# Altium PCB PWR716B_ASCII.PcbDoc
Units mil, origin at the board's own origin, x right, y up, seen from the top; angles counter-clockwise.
Board outline 2400 x 2000 mil, 2 copper layers (Top Layer, Bottom Layer), stack 64.8 mil thick; 38 components, 10 nets, 53 pads, 198 vias.
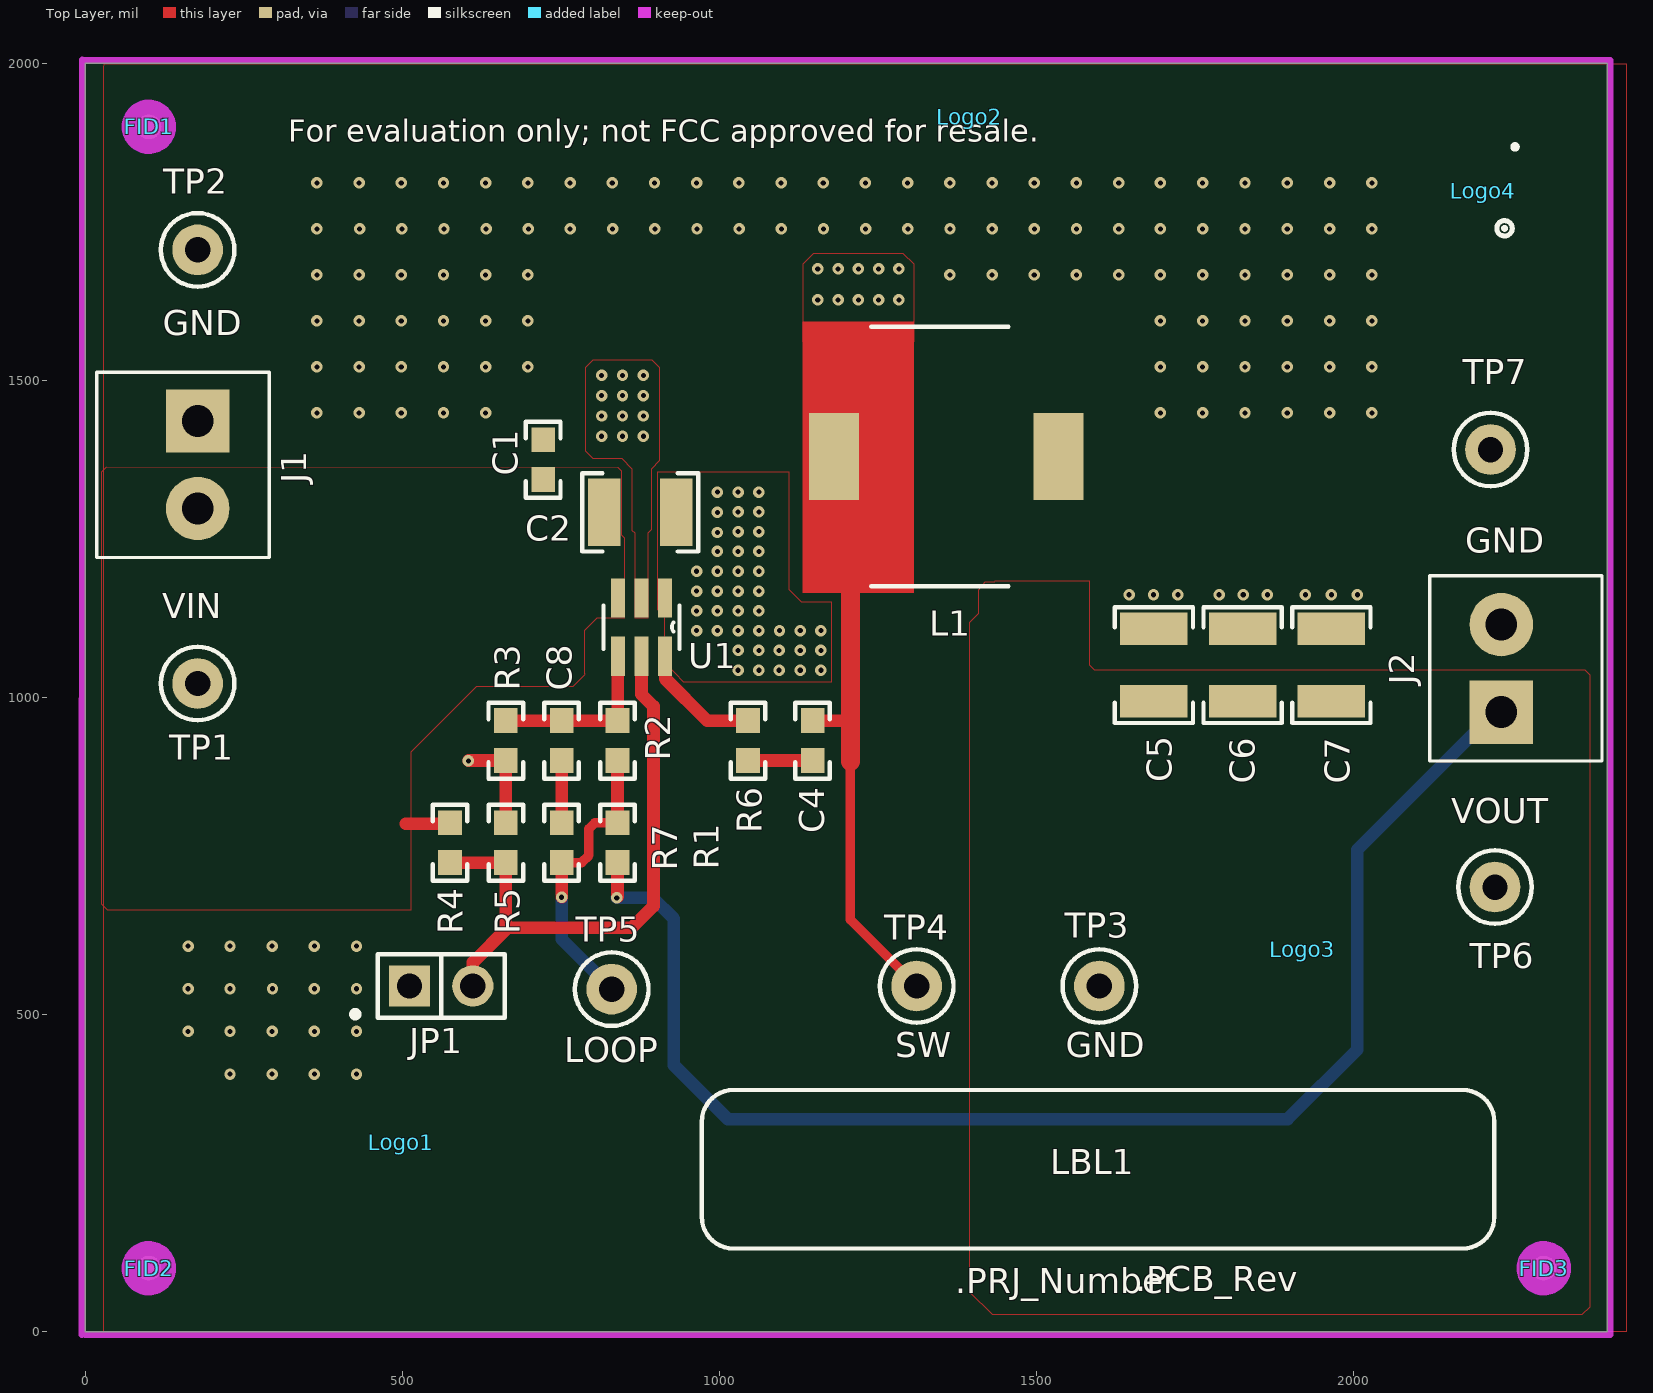
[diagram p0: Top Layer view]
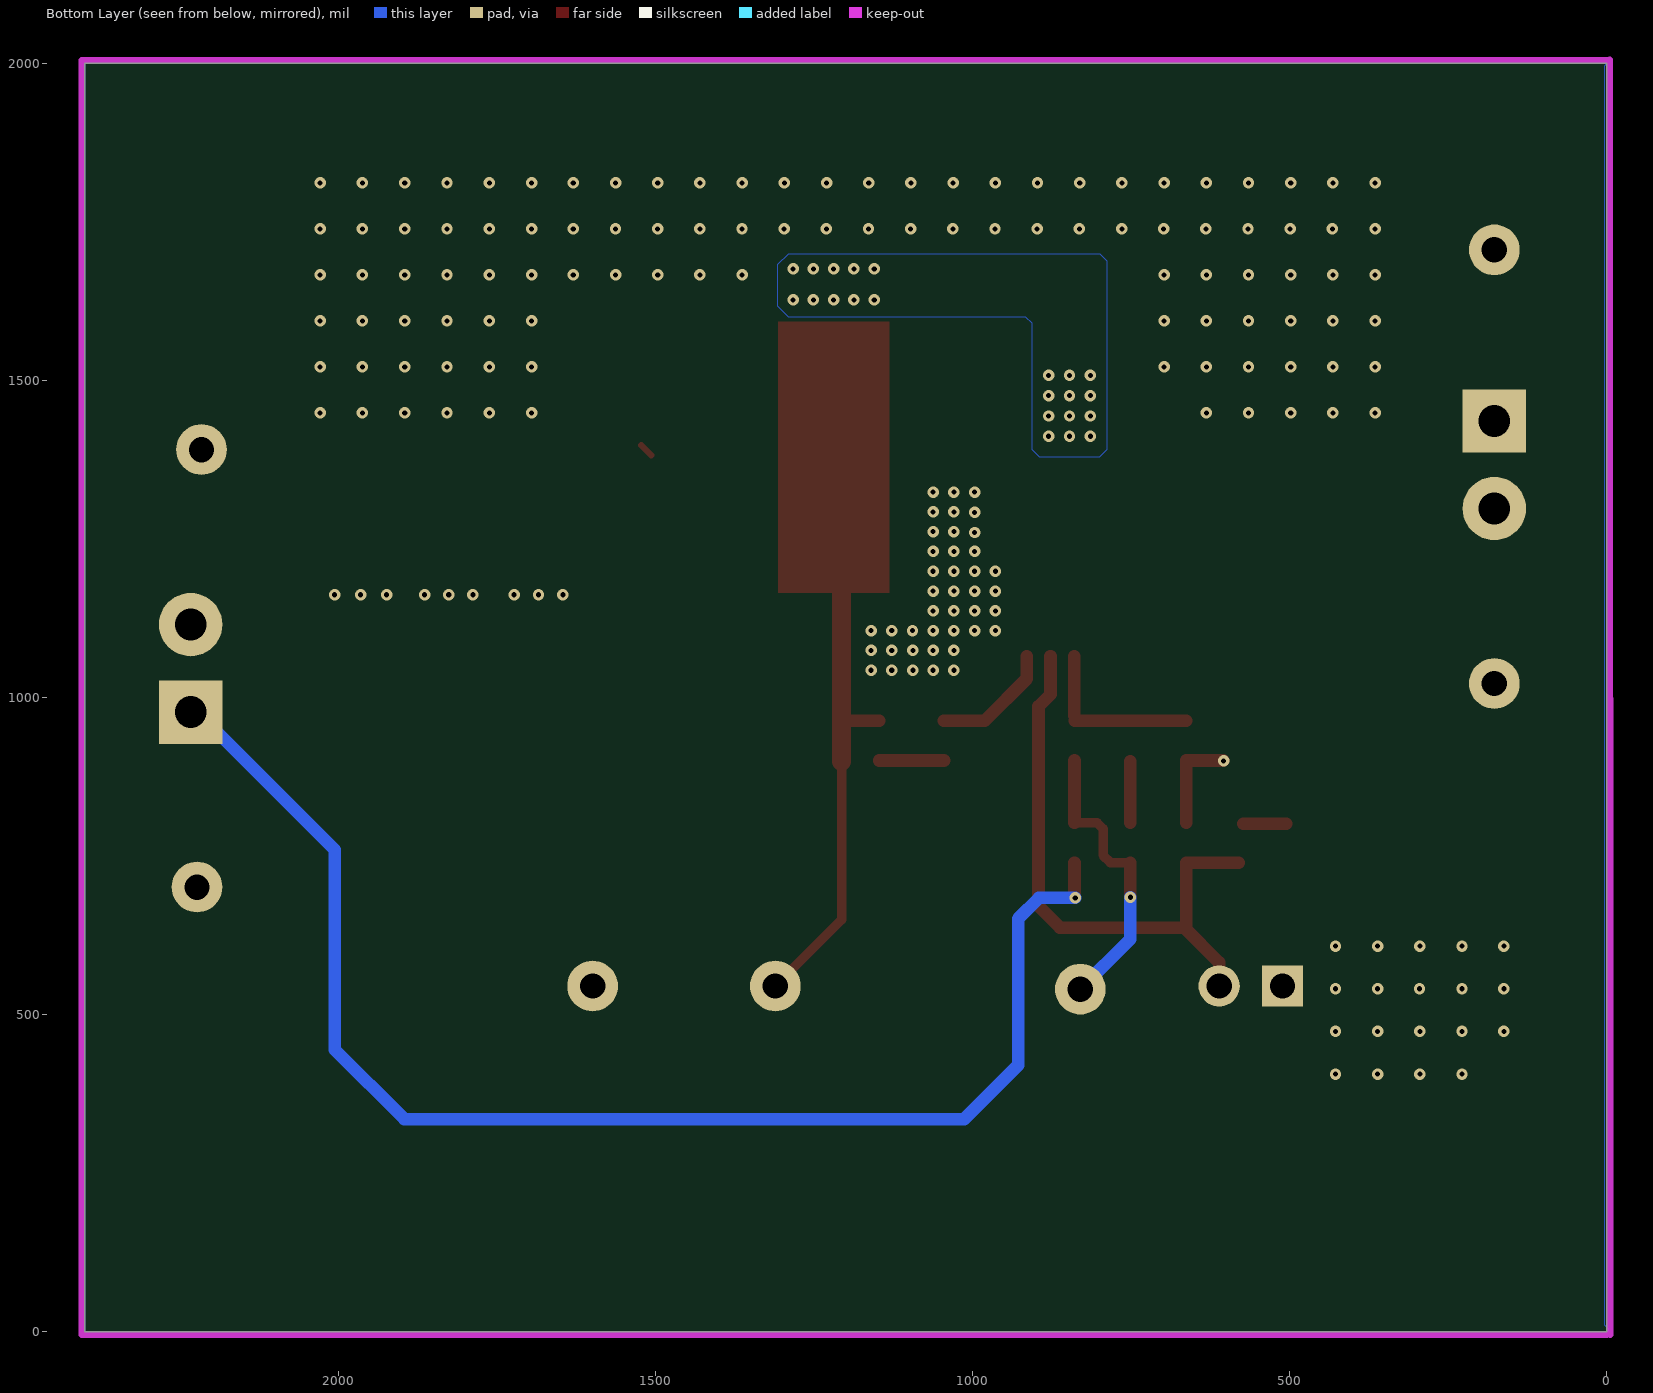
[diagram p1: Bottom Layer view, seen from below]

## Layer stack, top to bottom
Top Solder: solder mask 0.4, Solder Resist, Dk 3.5
Top Layer: signal copper 2.8
Dielectric1: core 59.2, FR-4, Dk 4.8
Bottom Layer: signal copper 2.8
Bottom Solder: solder mask 0.4, Solder Resist, Dk 3.5

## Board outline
0,0 2400,0 2400,2000 0,2000

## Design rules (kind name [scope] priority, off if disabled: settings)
AcuteAngle [All] p0: scope1count=1 scope1_0_kind=Board scope1_0_value=Board scope2count=1 scope2_0_kind=Board scope2_0_value=Board commentlength=0 minimum=4.50000000000000E+0001
AcuteAngle [All] p1: minimum=4.50000000000000E+0001 checktracksonly=FALSE
AssemblyTestPointUsage [All] p0: scope1count=1 scope1_0_kind=Board scope1_0_value=Board scope2count=1 scope2_0_kind=Board scope2_0_value=Board commentlength=0
AssemblyTestPointUsage [All] p1: valid=2
AssemblyTestpoint [All] p0: scope1count=1 scope1_0_kind=Board scope1_0_value=Board scope2count=1 scope2_0_kind=Board scope2_0_value=Board commentlength=0
Clearance Clearance_Keepouts [All] p0 off: scope1count=1 scope1_0_kind=Board scope1_0_value=Board scope2count=1 scope2_0_kind=Board scope2_0_value=Board commentlength=99 gap=0 // Protel DXP Scope 2 Expression Was: ((IsTrack Or IsArc) And Not InPoly) And IsFree and IsKeepOut
Clearance Clearance_BoardEdge_MountingHoles [All] p0 off: scope1count=1 scope1_0_kind=Board scope1_0_value=Board scope2count=1 scope2_0_kind=Board scope2_0_value=Board commentlength=48 gap=40 // Protel DXP Scope 2 Expression Was: IsKeepOut
Clearance Clearance_BoardEdge_Poly [All] p0 off: scope1count=1 scope1_0_kind=Board scope1_0_value=Board scope2count=1 scope2_0_kind=Board scope2_0_value=Board commentlength=48 gap=25 // Protel DXP Scope 2 Expression Was: IsKeepOut
Clearance Clearance_BoardEdge [All] p0 off: scope1count=1 scope1_0_kind=Board scope1_0_value=Board scope2count=1 scope2_0_kind=Board scope2_0_value=Board commentlength=48 gap=75 // Protel DXP Scope 2 Expression Was: IsKeepOut
Clearance Clearance_Poly [All] p0 off: scope1count=1 scope1_0_kind=Board scope1_0_value=Board scope2count=1 scope2_0_kind=Board scope2_0_value=Board commentlength=48 gap=15 // Protel DXP Scope 1 Expression Was: InPolygon
Clearance [All] p0: scope1count=1 scope1_0_kind=Board scope1_0_value=Board scope2count=1 scope2_0_kind=Board scope2_0_value=Board commentlength=0 gap=15
Clearance Clearance_Keepouts [((IsTrack Or IsArc) And Not InPoly) And IsFree and IsKeepOut vs ((IsTrack Or IsArc) And Not InPoly) And IsFree and IsKeepOut] p1: gap=0 ignorepadtopadclearanceinfootprint=FALSE
Clearance Clearance_BoardEdge_MountingHoles [OnCopper and InComponentClass('Mounting Holes') vs IsKeepOut] p2: gap=40 ignorepadtopadclearanceinfootprint=FALSE except(0: Arc-Hole Track-Hole SMDPad-Hole THPad-Hole Via-Hole Fill-Hole Poly-Hole Region-Hole Text-Hole)
Clearance Clearance_BoardEdge_Poly [OnCopper and InPoly vs IsKeepOut] p3: gap=25 ignorepadtopadclearanceinfootprint=FALSE except(0: Arc-Hole Track-Hole SMDPad-Hole THPad-Hole Via-Hole Fill-Hole Poly-Hole Region-Hole Text-Hole)
Clearance Clearance_BoardEdge [OnCopper and Not InComponentClass('Logo') and not InComponentClass('FiducialMark') and not InRegion(1000,500,4000,800) and Not IsKeepout vs IsKeepOut] p4: gap=75 ignorepadtopadclearanceinfootprint=FALSE except(0: Arc-Hole Track-Hole SMDPad-Hole THPad-Hole Via-Hole Fill-Hole Poly-Hole Region-Hole Text-Hole)
Clearance Clearance_Poly [InPolygon] p5: gap=15 ignorepadtopadclearanceinfootprint=FALSE except(0: Arc-Hole Track-Hole SMDPad-Hole THPad-Hole Via-Hole Fill-Hole Poly-Hole Region-Hole Text-Hole)
Clearance [All] p6: gap=15 ignorepadtopadclearanceinfootprint=FALSE except(0: Arc-Hole Track-Hole SMDPad-Hole THPad-Hole Via-Hole Fill-Hole Poly-Hole Region-Hole Text-Hole)
ComponentClearance ComponentClearance_MountingHoles_FiducialMarks [All] p0: scope1count=1 scope1_0_kind=ComponentClass scope1_0_value="Mounting Holes" scope2count=1 scope2_0_kind=ComponentClass scope2_0_value=FiducialMark commentlength=0 gap=50 collisioncheckmode=3
ComponentClearance ComponentClearance_Shunt [All] p0: scope1count=1 scope1_0_kind=ComponentClass scope1_0_value=Header scope2count=1 scope2_0_kind=ComponentClass scope2_0_value=Shunt commentlength=0 gap=0 collisioncheckmode=3
ComponentClearance ComponentClearance_Logo [All] p0: scope1count=1 scope1_0_kind=ComponentClass scope1_0_value=Logo scope2count=1 scope2_0_kind=Board scope2_0_value=Board commentlength=0 gap=50 collisioncheckmode=3
ComponentClearance ComponentClearance_ScrewToNut [All] p0 off: scope1count=1 scope1_0_kind=Board scope1_0_value=Board scope2count=1 scope2_0_kind=Board scope2_0_value=Board commentlength=71 gap=5 collisioncheckmode=3 // Protel DXP Scope 2 Expression Was: (HasFootprint('Keystone_1902C'))
ComponentClearance ComponentClearance_MountingHoles [All] p0: scope1count=1 scope1_0_kind=ComponentClass scope1_0_value="Mounting Holes" scope2count=1 scope2_0_kind=Board scope2_0_value=Board commentlength=0 gap=250 collisioncheckmode=3
ComponentClearance ComponentClearance_SmallPassives [All] p0 off: scope1count=1 scope1_0_kind=Board scope1_0_value=Board scope2count=1 scope2_0_kind=Board scope2_0_value=Board commentlength=508 gap=20 collisioncheckmode=3 // Protel DXP Scope 2 Expression Was: HasFootprint('0201*') or HasFootprint('0402*') or HasFootprint('0508') or HasFootprint('0603*') or HasFootprint('0612') or HasFootprint('0805*') or HasFootprint('0815*') or HasFootprint('0830*') or HasFootprint('1206*') or HasFootprint('1210*') or HasFootprint('1808*') or HasFootprint('1812*') or HasFootprint('1825*') or HasFootprint('2010*') or HasFootprint('2220*') or HasFootprint('2225*') or HasFootprint('2512*') or HasFootprint('2728*') or HasFootprint('3518*')
ComponentClearance ComponentClearance_THtoSMT [All] p0 off: scope1count=1 scope1_0_kind=Board scope1_0_value=Board scope2count=1 scope2_0_kind=Board scope2_0_value=Board commentlength=53 gap=85 collisioncheckmode=3 // Protel DXP Scope 2 Expression Was: IsSMTComponent
ComponentClearance ComponentClearance_THtoTH [All] p0 off: scope1count=1 scope1_0_kind=Board scope1_0_value=Board scope2count=1 scope2_0_kind=Board scope2_0_value=Board commentlength=54 gap=118.11 collisioncheckmode=3 // Protel DXP Scope 2 Expression Was: IsThruComponent
ComponentClearance [All] p0: scope1count=1 scope1_0_kind=Board scope1_0_value=Board scope2count=1 scope2_0_kind=Board scope2_0_value=Board commentlength=0 gap=40 collisioncheckmode=3
ComponentClearance ComponentClearance_MountingHoles_FiducialMarks [InComponentClass('Mounting Holes') vs InComponentClass('FiducialMark')] p1: gap=50 collisioncheckmode=3 verticalgap=10 showdistances=FALSE
ComponentClearance ComponentClearance_Shunt [InComponentClass('Header') vs InComponentClass('Shunt')] p2: gap=0 collisioncheckmode=3 verticalgap=0 showdistances=FALSE
ComponentClearance ComponentClearance_Logo [InComponentClass('Logo')] p3: gap=50 collisioncheckmode=3 verticalgap=10 showdistances=FALSE
ComponentClearance ComponentClearance_ScrewToNut [(HasFootprint('NY PMS 440 0025 PH')) vs (HasFootprint('Keystone_1902C'))] p4: gap=5 collisioncheckmode=3 verticalgap=10 showdistances=FALSE
ComponentClearance ComponentClearance_MountingHoles [InComponentClass('Mounting Holes')] p5: gap=250 collisioncheckmode=3 verticalgap=100000 showdistances=FALSE
ComponentClearance ComponentClearance_SmallPassives [HasFootprint('0201*') or HasFootprint('0402*') or HasFootprint('0508') or HasFootprint('0603*') or HasFootprint('0612') or HasFootprint('0805*') or HasFootprint('0815*') or HasFootprint('0830*') or HasFootprint('1206*') or HasFootprint('1210*') or HasFootprint('1808*') or HasFootprint('1812*') or HasFootprint('1825*') or HasFootprint('2010*') or HasFootprint('2220*') or HasFootprint('2225*') or HasFootprint('2512*') or HasFootprint('2728*') or HasFootprint('3518*') vs HasFootprint('0201*') or HasFootprint('0402*') or HasFootprint('0508') or HasFootprint('0603*') or HasFootprint('0612') or HasFootprint('0805*') or HasFootprint('0815*') or HasFootprint('0830*') or HasFootprint('1206*') or HasFootprint('1210*') or HasFootprint('1808*') or HasFootprint('1812*') or HasFootprint('1825*') or HasFootprint('2010*') or HasFootprint('2220*') or HasFootprint('2225*') or HasFootprint('2512*') or HasFootprint('2728*') or HasFootprint('3518*')] p6: gap=20 collisioncheckmode=3 verticalgap=10 showdistances=FALSE
ComponentClearance ComponentClearance_THtoSMT [IsThruComponent vs IsSMTComponent] p7: gap=85 collisioncheckmode=3 verticalgap=30 showdistances=FALSE
ComponentClearance ComponentClearance_THtoTH [IsThruComponent vs IsThruComponent] p8: gap=118.11 collisioncheckmode=3 verticalgap=30 showdistances=FALSE
ComponentClearance [All] p9: gap=40 collisioncheckmode=3 verticalgap=10 showdistances=FALSE
DiffPairsRouting [All] p0: scope1count=1 scope1_0_kind=Board scope1_0_value=Board scope2count=1 scope2_0_kind=Board scope2_0_value=Board commentlength=0
DiffPairsRouting [All] p1: maxlimit=100 minlimit=10 mostfreqgap=10 toplayer_minwidth=15 toplayer_maxwidth=15 toplayer_prefwidth=15 bottomlayer_minwidth=15 bottomlayer_maxwidth=15 bottomlayer_prefwidth=15 maxuncoupledlength=1000
FabricationTestPointUsage TestPointUsage [All] p0: scope1count=1 scope1_0_kind=Board scope1_0_value=Board scope2count=1 scope2_0_kind=Board scope2_0_value=Board commentlength=0 valid=2 allowmultiple=FALSE
FabricationTestPointUsage TestPointUsage [All] p1: valid=2 allowmultiple=FALSE
FabricationTestpoint Testpoint [All] p0: scope1count=1 scope1_0_kind=Board scope1_0_value=Board scope2count=1 scope2_0_kind=Board scope2_0_value=Board commentlength=0 side=3 testpointundercomponent=TRUE minsize=40 maxsize=100 preferedsize=60 minholesize=0 maxholesize=40 preferedholesize=32 testpointgrid=1
FabricationTestpoint Testpoint [All] p1: side=3 testpointundercomponent=TRUE minsize=40 maxsize=100 preferedsize=60 minholesize=0 maxholesize=40 preferedholesize=32 testpointgrid=1 allowsidetop=TRUE allowsidebottom=TRUE usegrid=TRUE gridtolerance=0.01
FanoutControl Fanout_LCC [All] p0 off: scope1count=1 scope1_0_kind=Board scope1_0_value=Board scope2count=1 scope2_0_kind=Board scope2_0_value=Board commentlength=69 // Protel DXP Scope 1 Expression Was: IsLCC   Fanout_LCC (Default Rule)
FanoutControl Fanout_BGA [All] p0 off: scope1count=1 scope1_0_kind=Board scope1_0_value=Board scope2count=1 scope2_0_kind=Board scope2_0_value=Board commentlength=69 // Protel DXP Scope 1 Expression Was: IsBGA   Fanout_BGA (Default Rule)
FanoutControl Fanout_SOIC [All] p0 off: scope1count=1 scope1_0_kind=Board scope1_0_value=Board scope2count=1 scope2_0_kind=Board scope2_0_value=Board commentlength=71 // Protel DXP Scope 1 Expression Was: IsSOIC   Fanout_SOIC (Default Rule)
FanoutControl Fanout_Default [All] p0: scope1count=1 scope1_0_kind=Board scope1_0_value=Board scope2count=1 scope2_0_kind=Board scope2_0_value=Board commentlength=30 // Fanout_Default (Default Rule)
FanoutControl Fanout_Small [All] p0 off: scope1count=1 scope1_0_kind=Board scope1_0_value=Board scope2count=1 scope2_0_kind=Board scope2_0_value=Board commentlength=84 // Protel DXP Scope 1 Expression Was: (CompPinCount < 5)   Fanout_Small (Default Rule)
FanoutControl Fanout_LCC [IsLCC] p1: bgadir=Out bgaviamode=Centered fanoutstyle=Auto fanoutdirection=Alternating viagrid=1 // Fanout_LCC (Default Rule)
FanoutControl Fanout_BGA [IsBGA] p2: bgadir=Out bgaviamode=Centered fanoutstyle=Auto fanoutdirection=Alternating viagrid=1 // Fanout_BGA (Default Rule)
FanoutControl Fanout_Default [All] p4: bgadir=Out bgaviamode=Centered fanoutstyle=Auto fanoutdirection=Alternating viagrid=1 // Fanout_Default (Default Rule)
FanoutControl Fanout_Small [(CompPinCount < 5)] p5: bgadir=Out bgaviamode=Centered fanoutstyle=Auto fanoutdirection=OutThenIn viagrid=1 // Fanout_Small (Default Rule)
Height [All] p0: scope1count=1 scope1_0_kind=Board scope1_0_value=Board scope2count=1 scope2_0_kind=Board scope2_0_value=Board commentlength=0
HoleSize [All] p0: scope1count=1 scope1_0_kind=Board scope1_0_value=Board scope2count=1 scope2_0_kind=Board scope2_0_value=Board commentlength=0 absolutevalues=TRUE maxlimit=251 minlimit=8 maxpercent=80.000 minpercent=20.000
HoleSize [All] p1: absolutevalues=TRUE maxlimit=251 minlimit=8 maxpercent=80.000 minpercent=20.000
HoleToHoleClearance [All] p0: scope1count=1 scope1_0_kind=Board scope1_0_value=Board scope2count=1 scope2_0_kind=Board scope2_0_value=Board commentlength=0
LayerPairs [All] p0: scope1count=1 scope1_0_kind=Board scope1_0_value=Board scope2count=1 scope2_0_kind=Board scope2_0_value=Board commentlength=0 enforce=TRUE
MinimumAnnularRing MinimumAnnularRing_ThermalPadVias [All] p0 off: scope1count=1 scope1_0_kind=Board scope1_0_value=Board scope2count=1 scope2_0_kind=Board scope2_0_value=Board commentlength=63 minimumring=5.91 // Protel DXP Scope 1 Expression Was: IsVia and InAnyComponent
MinimumAnnularRing [All] p0: scope1count=1 scope1_0_kind=Board scope1_0_value=Board scope2count=1 scope2_0_kind=Board scope2_0_value=Board commentlength=0 minimumring=5
MinimumAnnularRing MinimumAnnularRing_ThermalPadVias [IsVia and InAnyComponent] p1: minimumring=5.91
MinimumAnnularRing [All] p2: minimumring=5
MinimumSolderMaskSliver MinimumSolderMaskSliver_Logo [All] p0: scope1count=1 scope1_0_kind=ComponentClass scope1_0_value=Logo scope2count=1 scope2_0_kind=ComponentClass scope2_0_value=Logo commentlength=0
MinimumSolderMaskSliver [All] p0: scope1count=1 scope1_0_kind=Board scope1_0_value=Board scope2count=1 scope2_0_kind=Board scope2_0_value=Board commentlength=0
MinimumSolderMaskSliver MinimumSolderMaskSliver_Logo [InComponentClass('Logo') vs InComponentClass('Logo')] p1: minsoldermaskwidth=0.7
MinimumSolderMaskSliver [All] p2: minsoldermaskwidth=3.94
NetAntennae [All] p0: scope1count=1 scope1_0_kind=Board scope1_0_value=Board scope2count=1 scope2_0_kind=Board scope2_0_value=Board commentlength=0
PasteMaskExpansion [All] p0: scope1count=1 scope1_0_kind=Board scope1_0_value=Board scope2count=1 scope2_0_kind=Board scope2_0_value=Board commentlength=0 expansion=0
PlaneClearance [All] p0: scope1count=1 scope1_0_kind=Board scope1_0_value=Board scope2count=1 scope2_0_kind=Board scope2_0_value=Board commentlength=0 clearance=20
PlaneConnect [All] p0: scope1count=1 scope1_0_kind=Board scope1_0_value=Board scope2count=1 scope2_0_kind=Board scope2_0_value=Board commentlength=0 planeconnectstyle=Relief reliefexpansion=10 reliefentries=4 reliefconductorwidth=10 reliefairgap=10
PlaneConnect [All] p1: planeconnectstyle=Relief reliefexpansion=10 reliefentries=4 reliefconductorwidth=10 reliefairgap=10
PolygonConnect [All] p0: scope1count=1 scope1_0_kind=Board scope1_0_value=Board scope2count=1 scope2_0_kind=Board scope2_0_value=Board commentlength=0 connectstyle=Direct reliefconductorwidth=10 reliefentries=4 polygonreliefangle="90 Angle"
PolygonConnect [All] p1: connectstyle=Direct reliefconductorwidth=10 reliefentries=4 polygonreliefangle="90 Angle" airgapwidth=10
RoutingCorners [All] p0: scope1count=1 scope1_0_kind=Board scope1_0_value=Board scope2count=1 scope2_0_kind=Board scope2_0_value=Board commentlength=0 cornerstyle=45-Degree minsetback=100 maxsetback=100
RoutingLayers [All] p0: scope1count=1 scope1_0_kind=Board scope1_0_value=Board scope2count=1 scope2_0_kind=Board scope2_0_value=Board commentlength=0 top layer=Automatic bottom layer=Automatic
RoutingPriority [All] p0: scope1count=1 scope1_0_kind=Board scope1_0_value=Board scope2count=1 scope2_0_kind=Board scope2_0_value=Board commentlength=0
RoutingTopology [All] p0: scope1count=1 scope1_0_kind=Board scope1_0_value=Board scope2count=1 scope2_0_kind=Board scope2_0_value=Board commentlength=0 topology=Shortest
RoutingVias ThermalPadVias [All] p0 off: scope1count=1 scope1_0_kind=Board scope1_0_value=Board scope2count=1 scope2_0_kind=Board scope2_0_value=Board commentlength=63 holewidth=7.87 width=19.68 viastyle="Through Hole" minholewidth=7.87 minwidth=15.69 maxholewidth=12.99 maxwidth=23.62 // Protel DXP Scope 1 Expression Was: IsVia and InAnyComponent
RoutingVias [All] p0: scope1count=1 scope1_0_kind=Board scope1_0_value=Board scope2count=1 scope2_0_kind=Board scope2_0_value=Board commentlength=0 holewidth=8 width=16 viastyle="Through Hole" minholewidth=7.87 minwidth=15 maxholewidth=40 maxwidth=65
RoutingVias ThermalPadVias [IsVia and InAnyComponent] p1: holewidth=7.87 width=19.68 viastyle="Through Hole" minholewidth=7.87 minwidth=15.69 maxholewidth=12.99 maxwidth=23.62
RoutingVias [All] p2: holewidth=8 width=16 viastyle="Through Hole" minholewidth=7.87 minwidth=15 maxholewidth=40 maxwidth=65
ShortCircuit [All] p0: scope1count=1 scope1_0_kind=Board scope1_0_value=Board scope2count=1 scope2_0_kind=Board scope2_0_value=Board commentlength=0 allowed=FALSE
SilkToBoardRegionClearance [All] p0 off: scope1count=1 scope1_0_kind=Board scope1_0_value=Board scope2count=1 scope2_0_kind=Board scope2_0_value=Board commentlength=130 // Protel DXP Scope 1 Expression Was: Not ((IsComment or IsDesignator) And (Hide <> 'False')) and not InRegion(1000,500,4000,800)
SilkToBoardRegionClearance [Not ((IsComment or IsDesignator) And (Hide <> 'False')) and not InRegion(1000,500,4000,800)] p1:
SilkToSilkClearance SilkToSilkClearance_Pb-FreeLogo [All] p0 off: scope1count=1 scope1_0_kind=Board scope1_0_value=Board scope2count=1 scope2_0_kind=Board scope2_0_value=Board commentlength=120 // Protel DXP Scope 2 Expression Was: (HasFootprint('Pb-Free_Overlay_Medium') OR HasFootprint('Pb-Free_Overlay_Small'))
SilkToSilkClearance [All] p0: scope1count=1 scope1_0_kind=Board scope1_0_value=Board scope2count=1 scope2_0_kind=Board scope2_0_value=Board commentlength=0
SilkToSilkClearance SilkToSilkClearance_Pb-FreeLogo [(HasFootprint('Pb-Free_Overlay_Medium') OR HasFootprint('Pb-Free_Overlay_Small')) vs (HasFootprint('Pb-Free_Overlay_Medium') OR HasFootprint('Pb-Free_Overlay_Small'))] p1: silktosilkclearance=0
SilkToSilkClearance [All] p2: silktosilkclearance=5
SilkToSolderMaskClearance "Silk to Solder Mask Opening" [All] p0: scope1count=1 scope1_0_kind=Board scope1_0_value=Board scope2count=1 scope2_0_kind=Board scope2_0_value=Board commentlength=0
SilkToSolderMaskClearance "Silk to Solder Mask Opening" [All] p1: minsilkscreentomaskgap=3 clearancetoexposedcopper=FALSE
SolderMaskExpansion [All] p0: scope1count=1 scope1_0_kind=Board scope1_0_value=Board scope2count=1 scope2_0_kind=Board scope2_0_value=Board commentlength=0 expansion=1.97
SolderMaskExpansion [All] p1: expansion=1.97
UnRoutedNet [All] p0: scope1count=1 scope1_0_kind=Board scope1_0_value=Board scope2count=1 scope2_0_kind=Board scope2_0_value=Board commentlength=0
UnpouredPolygon [All] p0: scope1count=1 scope1_0_kind=Board scope1_0_value=Board scope2count=1 scope2_0_kind=Board scope2_0_value=Board commentlength=0
Width [All] p0: scope1count=1 scope1_0_kind=Board scope1_0_value=Board scope2count=1 scope2_0_kind=Board scope2_0_value=Board commentlength=0 maxlimit=100 minlimit=6 preferedwidth=10
Width [All] p1: maxlimit=100 minlimit=6 preferedwidth=10 checkconnectedcopper=TRUE
15 further rules are at their usual default settings.

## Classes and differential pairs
component class Header: JP1
component class PWR716A: C1 C2 C4 C5 C6 C7 C8 J1 J2 JP1 L1 R1 R2 R3 R4 R5 R6 R7 TP1 TP2 TP3 TP4 TP5 TP6 TP7 U1
component class Logo: Logo1
component class PWR716A_Hardware: FID1 FID2 FID3 LBL1 Logo1 Logo2 Logo3 Logo4 ZZ1 ZZ2 ZZ3 ZZ4
component class FiducialMark: FID1 FID2 FID3
component class AssemblyNote: ZZ1 ZZ2 ZZ3 ZZ4
component class Label: LBL1

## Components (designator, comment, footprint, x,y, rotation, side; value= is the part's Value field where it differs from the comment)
C1 "GRM188R61E104KA01D" 0603 722,1375 r90 top
C2 "GRM32ER7YA106KA12L" 1210 875,1292 r180 top
C4 "0.1uF" 0603 1147,932 r90 top
C5 "GRM32ER71E226KE15L" 1210 1685,1051 r270 top
C6 "GRM32ER71E226KE15L" 1210 1825,1051 r270 top
C7 "GRM32ER71E226KE15L" 1210 1965,1051 r270 top
C8 "GRM1885C1H750JA01D" 0603 751,932 r90 top
FID1 "Fiducial" Fiducial10-20 100,1900 r0 top
FID2 "Fiducial" Fiducial10-20 100,100 r0 top
FID3 "Fiducial" Fiducial10-20 2300,100 r0 top
J1 "ED555/2DS" TERM_BLK_ED555-2DS 177,1436 r270 top
J2 "ED555/2DS" TERM_BLK_ED555-2DS 2233,977 r90 top
JP1 "TSW-102-07-G-S" TSW-102-07-G-S 561,545 r0 top
L1 "7447714150" WE-PD-1050 1357.41,1380 r0 top
LBL1 "Size: 1.25\" x 0.25\"" Label_1250x250 1597,256 r180 top
Logo1 "Texas Instruments" TI_Stacked_Overlay_Small 497,298 r0 top
Logo2 "FCC disclaimer" FCC_disclaimer 1394,1916 r0 top
Logo3 "CE Mark" CE_Mark_5mm 1919,603 r0 top
Logo4 "WEEE logo" WEEE_Minimum 2204,1798.25 r0 top
R1 "CRCW060349R9FKEA" 0603 839,771 r270 top
R2 "CRCW0603100KFKEA" 0603 839,932 r270 top
R3 "CRCW060313K3FKEA" 0603 663,932 r90 top
R4 "CRCW0603510KJNEA" 0603 575,771 r90 top
R5 "CRCW0603105KFKEA" 0603 663,771 r270 top
R6 "ERJ-3GEY0R00V" 0603 1045,932 r270 top
R7 "ERJ-3GEY0R00V" 0603 751,771 r270 top
TP1 "5000" Keystone5000 177,1022 r0 top
TP2 "5001" Keystone5001 177,1706 r0 top
TP3 "5001" Keystone5001 1599,545 r90 top
TP4 "5004" Keystone5004 1311,545 r0 top
TP5 "5002" Keystone5002 830,540 r0 top
TP6 "5000" Keystone5000 2223,701 r0 top
TP7 "5001" Keystone5001 2216,1391 r0 top
U1 "TPS54202DDCR" DDC0006A_N 877,1111 r270 top
ZZ1 "This Assembly Note is for PCB labels only" AssemblyNoteLabel 185,3938 r0 top
ZZ2 "These assemblies are ESD sensitive, ESD precautions shall be observed." AssemblyNote 185,3829.11 r0 top
ZZ3 "These assemblies must be clean and free from flux and all contaminants. Use of no clean flux is not acceptable." AssemblyNote 185,3740.56 r0 top
ZZ4 "These assemblies must comply with workmanship standards IPC-A-610 Class 2, unless otherwise specified." AssemblyNote 185,3652 r0 top

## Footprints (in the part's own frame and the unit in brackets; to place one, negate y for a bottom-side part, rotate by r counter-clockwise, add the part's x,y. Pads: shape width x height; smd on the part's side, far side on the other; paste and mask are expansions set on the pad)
0603 [mm] "0603 from SM-752 data"
  rect 1x0.95 smd: 1(-0.8,0) 2(0.8,0)
  silkscreen extent -1.52,-0.69 1.52,0.69
1210 [mm] "1210 from SM-752 data"
  rect 1.3x2.7 smd: 1(-1.45,0) 2(1.45,0)
  silkscreen extent -2.32,-1.57 2.32,1.57
AssemblyNote [mil] "Assembly Note"
AssemblyNoteLabel [mil] "Assembly Note for PCB Labels"
CE_Mark_5mm [mil] "Minimum text height for CE Mark"
DDC0006A_N [mil]
  rect 62x22 smd: 1(-46,37.4) 2(-46,0) 3(-46,-37.4) 4(46,-37.4) 5(46,0) 6(46,37.4)
  silkscreen extent -35,-60 35,60
FCC_disclaimer [mil]
Fiducial10-20 [mm]
  round 1 smd paste-0.5 mask+0: 1(0,0)
  Top Layer keep-out circle w1.178: c0,0 r0.5
Keystone5000 [mil] "For Keystone 500x miniature loop terminals"
  round 80 hole 40: 1(0,0)
  silkscreen extent -58,-58 58,58
Keystone5001 [mil] "For Keystone 500x miniature loop terminals"
  round 80 hole 40: 1(0,0)
  silkscreen extent -58,-58 58,58
Keystone5002 [mil] "For Keystone 500x miniature loop terminals"
  round 80 hole 40: 1(0,0)
  silkscreen extent -58,-58 58,58
Keystone5004 [mil] "For Keystone 500x miniature loop terminals"
  round 80 hole 40: 1(0,0)
  silkscreen extent -58,-58 58,58
Label_1250x250 [mil] "Thermal Transfer Labels"
  round 1 on Mech13: 0(0,0)
  silkscreen extent -625,-125 625,125
TERM_BLK_ED555-2DS [mil]
  rect 100x100 hole 50: 1(0,0)
  round 100 hole 50: 2(138,0)
  silkscreen extent -77,-159 215,113
TI_Stacked_Overlay_Small [mil]
TSW-102-07-G-S [mm] "Samtec 100mil, 1x2, 230 mil above insulator"
  rect 1.65x1.65 hole 1.016 mask+0: 1(-1.27,0)
  round 1.65 hole 1.016 mask+0: 2(1.27,0)
  silkscreen extent -3.56,-1.27 2.54,1.27
WE-PD-1050 [mm] "WERTH"
  rect 2x3.5 smd: 1(-4.5,0) 2(4.5,0)
  silkscreen extent -3,-5.2 2.5,5.2
WEEE_Minimum [mil] "WEEElie bin"
  silkscreen extent 22,-71 54,74

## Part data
C1: "CAP, CERM, 0.1uF, 25V, +/-10%, X5R, 0603"
C2: "CAP, CERM, 10 µF, 35 V, +/- 10%, X7R, 1210"
C4: library part GRM188R61E104KA01D, "CAP, CERM, 0.1uF, 25V, +/-10%, X5R, 0603"
C5 C6 C7: "CAP, CERM, 22 µF, 25 V, +/- 10%, X7R, 1210"
C8: "CAP, CERM, 75 pF, 50 V, +/- 5%, C0G/NP0, 0603"
FID1 FID2 FID3: "Fiducial mark.  There is nothing to buy or mount."
J1 J2: "Terminal Block, 6A, 3.5mm Pitch, 2-Pos, TH"
JP1: "Header, 100mil, 2x1, Gold, TH"
L1: "Inductor, Shielded Drum Core, Ferrite, 15 µH, 3.5 A, 0.036 ohm, SMD"
LBL1: library part THT-13-457-10, "Thermal Transfer Printable Labels, 1.250\" W x 0.250\" H - 10,000 per roll"
Logo1: library part TI_Logo, "Texas Instrument Corporate Signature"
Logo2: library part FCC_disclaimer, "FCC_disclaimer"
Logo3: library part CMP-0074844-1
Logo4: library part CMP-0074769-1
R1: "RES, 49.9, 1%, 0.1 W, 0603"
R2: "RES, 100 k, 1%, 0.1 W, 0603"
R3: "RES, 13.3 k, 1%, 0.1 W, 0603"
R4: "RES, 510 k, 5%, 0.1 W, 0603"
R5: "RES, 105 k, 1%, 0.1 W, 0603"
R6 R7: "RES, 0 ohm, 5%, 0.1W, 0603"
TP1 TP6: "Test Point, Miniature, Red, TH"
TP2 TP3 TP7: "Test Point, Miniature, Black, TH"
TP4: "Test Point, Miniature, Yellow, TH"
TP5: "Test Point, Miniature, White, TH"
U1: "4.5-V TO 28-V INPUT, 2-A OUTPUT, EMI FRIENDLY SYNCHRONUOUS STEP-DOWN CONVERTOR, DDC0006A"
ZZ1: library part AssemblyNoteLabel
ZZ2 ZZ3 ZZ4: library part AssemblyNote

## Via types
v1: diameter 18, hole 8, Top Layer to Bottom Layer, 198 vias

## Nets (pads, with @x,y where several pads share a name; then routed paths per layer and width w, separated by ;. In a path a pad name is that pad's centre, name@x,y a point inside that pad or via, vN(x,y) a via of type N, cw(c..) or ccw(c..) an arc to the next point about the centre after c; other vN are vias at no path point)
BOOT: R6.1 U1.6 | length 191.4
  Top Layer w20: U1.6 914.4,1029.6 980.5,963.5 ; 982.5,963.5 R6.1
EN: JP1.2 R4.1 R5.2 U1.5 | length 948.9
  Top Layer w10: 663,640 666,637 ; 830,637 831,636
  Top Layer w20: R4.1@580,739.5 R5.2 663,640 ; JP1.2 611,582 666,637 830,637 862,637 896,671 896,986 877,1005 U1.5
GND: C1.2 C2.1 C5.1 C6.1 C7.1 J1.1 J2.2 JP1.1 R3.1 R5.1 TP2.1 TP3.1 TP7.1 U1.1 | length 156.5
  Top Layer w20: v1@604.5,900.5 R3.1 R5.1
  other v1: 228,406 294.5,406 361,406 427.5,406 162,473.33 228,473.33 294.5,473.33 361,473.33 427.5,473.33 162,540.67 228,540.67 295,540.67 361,540.67 427.5,540.67 162,608 228,608 294.5,608 361,608 427.5,608 604,900 1029.33,1043 1062,1043 1094,1043 1127.33,1043 1160,1043 1029.33,1074.22 1062,1074.22 1094,1074.22 1127.33,1074.22 1160,1074.22 964,1105.44 996.67,1105.44 1029.33,1105.44 1062,1105.44 1094.67,1105.44 1127.33,1105.44 1160,1105.44 964,1136.67 996.67,1136.67 1029.33,1136.67 1062,1136.67 1646,1162 1684.5,1162 1723,1162 1788,1162 1826,1162 1864,1162 1924,1162 1965,1162 2006,1162 964,1167.89 996.67,1167.89 1029.33,1167.89 1062,1167.89 964,1199.11 996.67,1199.11 1029.33,1199.11 1062,1199.11 996.67,1230.33 1029.33,1230.33 1062,1230.33 996.67,1260.19 1029.33,1261.56 1062,1261.56 996.67,1292.09 1029.33,1292.78 1062,1292.78 996.67,1324 1029.33,1324 1062,1324 365,1449 431.55,1449 498.11,1449 564.66,1449 631.21,1449 1695.34,1449 1762.03,1449 1828.73,1449 1895.43,1449 1962.12,1449 2028.82,1449 365,1521.5 431.55,1521.5 498.11,1521.5 564.66,1521.5 631.21,1521.5 697.76,1521.5 1695.34,1521.5 1762.03,1521.5 1828.73,1521.5 1895.43,1521.5 1962.12,1521.5 2028.82,1521.5 365,1594 431.55,1594 498.11,1594 564.66,1594 631.21,1594 697.76,1594 1695.34,1594 1762.03,1594 1828.73,1594 1895.43,1594 1962.12,1594 2028.82,1594 365,1666.5 431.55,1666.5 498.11,1666.5 564.66,1666.5 631.21,1666.5 697.76,1666.5 1363.29,1666.5 1429.84,1666.5 1496.39,1666.5 1562.95,1666.5 1629.64,1666.5 1695.34,1666.5 1762.03,1666.5 1828.73,1666.5 1895.43,1666.5 1962.12,1666.5 2028.82,1666.5 365,1739 432.5,1739 499,1739 565.5,1739 632,1739 698.5,1739 764.32,1739 831.5,1739 898,1739 964.5,1739 1031,1739 1097.5,1739 1164,1739 1230.5,1739 1297,1739 1363.5,1739 1430,1739 1496.5,1739 1563,1739 1629.64,1739 1695.34,1739 1762.03,1739 1828.73,1739 1895.43,1739 1962.12,1739 2028.82,1739 365,1811.5 431.55,1811.5 498.11,1811.5 564.66,1811.5 631.21,1811.5 697.76,1811.5 764.32,1811.5 830.87,1811.5 897.42,1811.5 963.97,1811.5 1030.53,1811.5 1097.08,1811.5 1163.63,1811.5 1230.18,1811.5 1296.74,1811.5 1363.29,1811.5 1429.84,1811.5 1496.39,1811.5 1562.95,1811.5 1629.64,1811.5 1695.34,1811.5 1762.03,1811.5 1828.73,1811.5 1895.43,1811.5 1962.12,1811.5 2028.82,1811.5
NetC4_1: C4.1 R6.2 | length 102
  Top Layer w20: R6.2 C4.1
NetC8_1: C8.1 R7.1 | length 100.1
  Top Layer w10: C8.1 751,899 C8.1@752.5,900.5
  Top Layer w20: R7.1 C8.1@751,899
NetR1_1: R1.1 R2.2 R7.2 TP5.1 | length 468.9
  Top Layer w15: R7.2 782.5,739.5 794,751 794,793 803.5,802.5 R1.1
  Top Layer w20: v1(751,685) R7.2 ; R1.1 R2.2
  Bottom Layer w20: v1(751,685) 751,619 TP5.1
SW: C4.2 L1.1 TP4.1 U1.2 | length 933.2
  Top Layer w10: 1206.5,899 1206.5,898.5 1206.82,898.82
  Top Layer w15: 1206.5,898.5 1206.5,649.5 TP4.1
  Top Layer w20: C4.2 1201.31,963.5
  Top Layer w30: 1206.82,898.82 L1.1@1206.82,1380
  other v1: 814,1412 847,1412 880,1412 814,1444 847,1444 880,1444 814,1476 847,1476 880,1476 814,1508 847,1508 880,1508 1155,1627 1187,1627 1219,1627 1251,1627 1283,1627 1155,1676 1187,1676 1219,1676 1251,1676 1283,1676
VIN: C1.1 C2.2 J1.2 R4.2 TP1.1 U1.3 | length 67.5
  Top Layer w20: 505,801 R4.2@572.5,801
VOUT: C5.2 C6.2 C7.2 J2.1 L1.2 R1.2 TP6.1 | length 2192.9
  Top Layer w10: v1@838,685 v1@839,686 ; L1.2@1506.59,1382 L1.2@1522.59,1398
  Top Layer w20: v1@839,686 R1.2
  Bottom Layer w20: v1(838,684) 895,684 928,651 928,420 1013,335 1896,335 2006,445 2006,760 J2.1@2223,977
VSENSE: C8.2 R2.1 R3.2 U1.4 | length 270.1
  Top Layer w10: R2.1@838.5,963.5 R2.1@839,964
  Top Layer w20: R3.2 C8.2 R2.1@838.5,963.5 ; R2.1@839.6,971.09 U1.4
pads on no net: FID1.1 FID2.1 FID3.1 LBL1.0

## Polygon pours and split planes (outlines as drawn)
GND on Top Layer "Top Layer-No Net 1" (solid, remove dead copper, pour order 19): 908,1356 1109,1356 1109,1171 1129,1151 1176,1151 1176,1024 949,1024 944,1024 930,1038 914,1054 914,1129 912,1129 903,1138 903,1356
VOUT on Top Layer "Top Layer-No Net 3" (solid, remove dead copper, pour order 21): 1408,1169.5 1408,1132 1394,1118 1394,63 1430,27 2355,27 2361,27 2373,39 2373,1026 2373,1035 2365,1043 2090,1043 1803,1043 1598,1043 1592,1043 1584,1051 1584,1183 1434,1183 1433,1182 1418,1182
SW on Top Layer "Top Layer-No Net 5" (solid, remove dead copper, pour order 18): 1307,1563 1307,1683 1290,1700 1160,1700 1148,1700 1131,1683 1131,1562 1140,1553 1298,1553 1307,1562
SW on Top Layer "Top Layer-No Net 6" (solid, remove dead copper, pour order 17): 888,1126 888,1260 893,1265 893,1361 906,1374 906,1520 894,1532 800,1532 788,1520 788,1389 800,1377 846,1377 862,1361 862,1264 866,1260 866,1126 888,1126
VIN on Top Layer "Top Layer-No Net 7" (solid, remove dead copper, pour order 20): 850.71,1126 850.71,1251.29 846,1256 846,1357.14 840.26,1362.71 33,1363 25,1355 25,675 34.75,665.25 514,665.25 514,914.59 617.41,1018 769,1018 788,1037 787.46,1037.54 787.46,1076.1 787.46,1106.3 807.16,1126
GND on Top Layer "Top Layer-No Net" (solid, remove dead copper, pour order 22): 30,1999.5 2430,1999.5 2430,-0.5 30,-0.5 29,0.5 29,1993.5
SW on Bottom Layer "Top Layer-No Net 2" (solid, remove dead copper, pour order 23): 800,1379 846,1379 893,1379 894,1379 906,1391 906,1590 916,1600 1290,1600 1307,1617 1307,1630 1307,1683 1290,1700 800,1700 799,1700 788,1689 788,1391 800,1379
GND on Bottom Layer "Bottom Layer-No Net" (solid, remove dead copper, pour order 24): 0,2000 2400,2000 2400,0 -1,0 -4,3 3,10 3,1996

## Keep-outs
Keep-Out Layer:
  lines w10: -6,-5 -5,2006 2405,2005 2405,-5 0,-5
  text ".Layer_Name" at 577,-858.49 h60

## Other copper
Top Layer:
  rectangle net SW: 1131,1165 1307,1593
  text ".Layer_Name" at 577,-858.49 h60
Bottom Layer:
  text ".Layer_Name" at 577,-858.49 h60

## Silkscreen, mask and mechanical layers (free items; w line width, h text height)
Top Overlay:
  text "GND" at 122,1571 h40
  text "GND" at 2176,1228 h40
  text "VIN" at 121,1125 h40
  text "VOUT" at 2154,802 h40
  text "SW" at 1277,433 h40
  text "GND" at 1546,433 h40
  text "LOOP" at 755,425 h40
  text ".PCB_Rev" at 1656,64 h40
  text ".PRJ_Number" at 1372.01,60.12 h40
  text ".Layer_Name" at 577,-858.49 h60
Bottom Overlay:
  text ".Layer_Name" at 577,-858.49 h60
Top Paste:
  text ".Layer_Name" at 577,-858.49 h60
Bottom Paste:
  text ".Layer_Name" at 577,-858.49 h60
Top Solder:
  rectangle: 1138,1195 1300,1575
  rectangle: 1442,1195 1581,1575
  text ".Layer_Name" at 577,-858.49 h60
  text ".Layer_Name" at 577,-858.49 h60
Bottom Solder:
  text ".Layer_Name" at 577,-858.49 h60
Drill Guide:
  text ".Layer_Name" at 577,-858.49 h60
M1 Board Outline:
  lines w10: 0,0 0,2001 2400,2001 2400,0 0,0
  text ".Layer_Name" at 577,-858.49 h60
M2 Board Dimensions:
  rectangle: -0.5,-285.5 124.5,-160.5
  rectangle: 124.5,-410.5 499.5,-285.5
  lines w7: -0.5,-285.5 999.5,-285.5 ; 124.5,-410.5 124.5,-160.5 ; 249.5,-410.5 249.5,-160.5 ; 499.5,-410.5 499.5,-160.5 ; 749.5,-410.5 749.5,-160.5 ; -0.5,-410.5 999.5,-410.5 999.5,-160.5 -0.5,-160.5 -0.5,-410.5
  text ".Layer_Name" at 577,-858.49 h60
M3 3D STEP Top:
  text ".Layer_Name" at 577,-858.49 h60
M4 3D STEP Bottom:
  text ".Layer_Name" at 577,-858.49 h60
M5 Assembly Top:
  lines w10: -292,-930.17 6308,-930.17 ; -292,-726.83 6310,-726.83 ; -292,-523.5 -292,-1133.5 3713,-1133.5 6310,-1133.5 6310,-523.5 -291.5,-523.5 -291.5,-1133.5 1284,-1133.5 ; 2173,-1133.5 2173,-523.5 ; 3440,-726.83 3440,-523.5 ; 4280,-726.83 4280,-523.5 ; 4902,-1140 4902,-937.17
  text "COMPONENTS MARKED 'DNP' SHOULD NOT BE POPULATED." at 1153.5,-318.5 h60
  text "ASSEMBLY VARIANT:" at 1153,-434 h60
  text ".VariantName" at 2189,-434 h60
  text "PCB VIEWED FROM TOP SIDE" at -228.5,-655.67 h60
  text "BOARD #:" at 2248,-655.67 h60
  text ".PRJ_Number" at 2793.5,-655.67 h60
  text "REV:" at 3638,-655.67 h60
  text "B" at 3929.5,-655.67 h60
  text "SVN REV:" at 4476,-655.67 h60
  text ".VersionControl_RevNumber" at 4982,-655.67 h60
  text "IGNORE ->" at -228.5,-858.49 h60
  text "PLOT NAME =" at -228.5,-1064.34 h60
  text ".plot_File_Name" at 577,-1064.34 h60
  text "GENERATED    :" at 2250,-1064.34 h60
  text ".Print_Date" at 3119.5,-1064.34 h60
  text ".Print_Time" at 3848.5,-1064.34 h60
  text "TEXAS INSTRUMENTS" at 5113,-1064.34 h60
M6 Assembly Bottom:
  lines w10: -292.5,-727.33 6309.5,-727.33 ; -290.5,-930.67 6309.5,-930.67 ; 1115.5,-1140.5 1115.5,-937.67 ; 1737.5,-727.33 1737.5,-524 ; 2577.5,-727.33 2577.5,-524 ; 3844.5,-1134 3844.5,-524 ; 4733.5,-1134 6309,-1134 6309,-524 -292.5,-524 -292.5,-1134 2304.5,-1134 6309.5,-1134 6309.5,-524
  text "COMPONENTS MARKED 'DNP' SHOULD NOT BE POPULATED." at 6102,-318 h60
  text ".VariantName" at 5058,-434 h60
  text "ASSEMBLY VARIANT:" at 6097,-434 h60
  text ".VersionControl_RevNumber" at 1035.5,-656.17 h60
  text "SVN REV:" at 1541.5,-656.17 h60
  text "B" at 2088,-656.17 h60
  text "REV:" at 2379.5,-656.17 h60
  text ".PRJ_Number" at 3224,-656.17 h60
  text "BOARD #:" at 3769.5,-656.17 h60
  text "PCB VIEWED FROM BOTTOM SIDE" at 6246,-656.17 h60
  text "IGNORE ->" at 2547.85,-858.49 h60
  text "TEXAS INSTRUMENTS" at 904.5,-1064.84 h60
  text ".Print_Time" at 2169,-1064.84 h60
  text ".Print_Date" at 2898,-1064.84 h60
  text "GENERATED    :" at 3767.5,-1064.84 h60
  text ".plot_File_Name" at 5440.5,-1064.84 h60
  text "PLOT NAME =" at 6246,-1064.84 h60
M9 Title Sheet:
  lines w10: -491.5,1041.5 -291.5,1041.5 ; -491.5,3416.5 -291.5,3416.5 ; -491.5,5791.5 -291.5,5791.5 ; 2008.5,-1333.5 2008.5,-1133.5 ; 2008.5,7966.5 2008.5,8166.5 ; 4508.5,-1333.5 4508.5,-1133.5 ; 4508.5,7966.5 4508.5,8166.5 ; 6321,-1133.5 6321,-523.5 11303.5,-523.5 ; 7008.5,-1333.5 7008.5,-1133.5 ; 7008.5,7966.5 7008.5,8166.5 ; 9508.5,-1333.5 9508.5,-1133.5 ; 9508.5,7966.5 9508.5,8166.5 ; 11303.5,-1133.5 11303.5,-523.5 ; 11303.5,-823.5 14303.5,-823.5 ; 11303.5,-251.5 14303.5,-251.5 ; 11303.5,76.5 11303.5,-523.5 ; 11303.5,370.5 11303.5,2 14303.5,2 ; 12008.5,-1333.5 12008.5,-1133.5 ; 12008.5,7966.5 12008.5,8166.5 ; 12808.5,-1123.5 12808.5,-523.5 ; 14303.5,-523.5 11303.5,-523.5 ; 14304.5,249 11303.5,249 11303.5,643.5 11304.5,644.5 14308.5,644.5 ; 14308.5,66.5 14308.5,-1133.5 ; 14308.5,1041.5 14508.5,1041.5 ; 14308.5,3416.5 14508.5,3416.5 ; 14308.5,5791.5 14508.5,5791.5 ; 14308.5,-1133.5 14308.5,7966.5 -291.5,7966.5 -291.5,-1133.5 14308.5,-1133.5 ; -491.5,-1333.5 -491.5,8166.5 14508.5,8166.5 14508.5,-1333.5 -491.5,-1333.5
  text "1" at 739.84,8036.5 h70
  text "2" at 3235.5,8036.5 h70
  text "3" at 5724.84,8036.5 h70
  text "4" at 8231.51,8036.5 h70
  text "5" at 10730.5,8036.5 h70
  text "6" at 13235.5,8036.5 h70
  text "A" at -416.5,6893.5 h70
  text "A" at 14383.5,6893.5 h70
  text "B" at -416.5,4513.5 h70
  text "B" at 14383.5,4513.5 h70
  text "C" at -416.5,2138.5 h70
  text "C" at 14383.5,2138.5 h70
  text "PROJECT TITLE:" at 11351,163 h45
  text ".PRJ_Title" at 11385,50 h70
  text "DESIGNED FOR:" at 11344,-88 h45
  text ".PRJ_Customer" at 11388,-205 h70
  text "D" at -416.5,-231.5 h70
  text "D" at 14383.5,-231.5 h70
  text "FILE NAME:" at 11344,-346 h45
  text ".PCB_File_Name_No_Path" at 11388,-477 h70
  text "Texas Instruments (TI) and/or its licensors do not warrant the accuracy or completeness of this specification" at 6374,-605.34 h45
  text "ENGINEER:" at 11343.5,-613.5 h45
  text "LAYOUT BY:" at 12848.5,-613.5 h45
  text "or any information contained therein. TI and/or its licensors do not warrant that this design will meet" at 6329.01,-718 h45
  text ".PRJ_Engineer" at 11393.5,-768.49 h70
  text ".PCB_Layout" at 12899,-768.49 h70
  text "the specifications, will be suitable for your application or fit for any particular purpose, or will operate in" at 6329.01,-830.67 h45
  text ".Layer_Name" at 577,-858.49 h60
  text "ALTIUM DESIGNER VERSION:" at 12848.5,-923.5 h45
  text "an implementation. TI and/or its licensors do not warrant that the design is production worthy. You should" at 6329.01,-943.33 h45
  text "completely validate and test your design implementation to confirm the system functionality for your application." at 6374,-1056 h45
  text ".print_Scale" at 11393.5,-1056.83 h70
  text ".Application_BuildNumber" at 12899,-1056.83 h70
  text "1" at 739.84,-1263.5 h70
  text "2" at 3235.5,-1263.5 h70
  text "3" at 5724.84,-1263.5 h70
  text "4" at 8231.51,-1263.5 h70
  text "5" at 10730.5,-1263.5 h70
  text "6" at 13235.5,-1263.5 h70
M10 Fab Notes:
  drawing of 212 lines, arcs and shapes, not listed
  text "DESIGN INFORMATION" at 12381.02,6810 h60
  text "(REFER ALSO ARRAY/PANEL PROFILING INFORMATION)" at 12019.46,6648.29 h60
  text "BOARD SIZE" at 11333.46,6644 h60
  text "2000MIL" at 11795.78,6516.18 h60
  text "X" at 12301.46,6516.18 h60
  text "2400MIL" at 12532.78,6516.18 h60
  text "Number of Layers :" at 11736.46,6319 h60
  text "2" at 12831.27,6309 h60
  text "MIN. TRACK WIDTH:" at 11736.46,6180 h60
  text "8" at 12832.7,6180 h60
  text "MIL" at 12987.46,6180 h60
  text "MIN. CLEARANCE:" at 11736.46,6048 h60
  text "8" at 12832.7,6048 h60
  text "MIL" at 12987.46,6048 h60
  text "MIN. VIA PAD SIZE:" at 11736.46,5916 h60
  text "24" at 12802.71,5916 h60
  text "MIL" at 12987.46,5916 h60
  text "0.05mm (2MIL)" at 12431.46,5774.29 h60
  text "MINIMUM ANNULAR RING" at 11407.23,5770 h60
  text "EXTERNAL" at 13139.46,5770 h60
  text "PER" at 11607.23,5652 h60
  text "IPC-D-275 CLASS 2 LEVEL C" at 11827.23,5652 h60
  text "MIL, HOLES" at 13315.46,5539.71 h60
  text "+/-" at 12923,5539 h60
  text "+/-" at 13777,5539 h60
  text "REGISTRATION TOLERANCES:" at 11407.23,5534 h60
  text "METAL" at 12607,5534 h60
  text "5" at 13183.2,5534 h60
  text "3" at 14016.2,5534 h60
  text "MIL" at 14132.46,5534 h60
  text "MATERIAL:" at 11332.46,5324.54 h60
  text "FR-4 High Tg" at 12318.9,5184.21 h60
  text "FR-408" at 11753.46,5175.64 h60
  text "X" at 12165.46,5175.64 h60
  text "OTHER" at 13241.46,5175.64 h60
  text "62 MIL (1.6mm) +/-10%" at 12073.56,5012.92 h60
  text "THICKNESS:" at 11407.23,5008.64 h60
  text "X" at 11945.4,5008.64 h60
  text "OTHER" at 13358.46,5008.64 h60
  text "TOLERANCE:" at 11407.23,4850.64 h60
  text "X" at 12246.53,4850.64 h60
  text "ANSI IPC-6012 TYPE 3 CLASS 2" at 12433.48,4850.64 h60
  text "OTHER +/-" at 12433.46,4694.64 h60
  text "BOW & TWIST:" at 11407.23,4537.64 h60
  text "X" at 12246.53,4537.64 h60
  text "ANSI IPC-6012 TYPE 3 CLASS 2" at 12433.48,4537.64 h60
  text "OTHER +/-" at 12433.46,4379.13 h60
  text "COPPER THICKNESS (FINISHED):" at 11332.46,4243.64 h60
  text "1.4MIL (1oz)" at 12212.46,4090.92 h60
  text "2MIL (1.4oz)" at 12979.46,4090.92 h60
  text "2.8MIL (2oz)" at 13706.46,4090.92 h60
  text "OUTER:" at 11689.46,4086.64 h60
  text "X" at 13572,4086 h60
  text "1.4MIL (1oz)" at 12212.46,3933.92 h60
  text "2.8MIL (2oz)" at 12979.46,3933.92 h60
  text "N/A" at 13706,3934.29 h60
  text "INNER SIGNAL:" at 11400.38,3929.64 h60
  text "X" at 13575,3926 h60
  text "DRILLING:" at 11332.46,3790.64 h60
  text "REFERENCE:" at 11407.23,3673.64 h60
  text "X" at 12055.46,3673.64 h60
  text "AS SHOWN" at 12242.46,3673.64 h60
  text "X" at 12956.46,3673.64 h60
  text "NC_DRILL FILES" at 13093.46,3673.64 h60
  text "PTH MIN COPPER THICKNESS:" at 11407.23,3515.64 h60
  text "X" at 12757.46,3515.64 h60
  text "1MIL" at 12894.46,3515.64 h60
  text "OTHER" at 13391.46,3515.64 h60
  text "BOARD FINISH:" at 11332.46,3356.64 h60
  text "SILKSCREEN:" at 11487.68,3238.64 h60
  text "X" at 12436.46,3238.64 h60
  text "TOP" at 12562.46,3238.64 h60
  text "BOTTOM" at 13073.46,3238.64 h60
  text "SILKSCREEN COLOR:" at 11487.68,3071.64 h60
  text "X" at 12435.42,3071.64 h60
  text "WHITE" at 12562.46,3071.64 h60
  text "OTHER" at 13073.46,3071.64 h60
  text "SOLDER RESIST COLOR:" at 11487.68,2901.64 h60
  text "X" at 12055.42,2742.44 h60
  text "GREEN" at 12182.46,2742.44 h60
  text "BLUE" at 12773.46,2742.44 h60
  text "OTHER" at 13311.46,2742.44 h60
  text "X" at 12205,2556 h60
  text "IMMERSION GOLD (ENIG)" at 12393.46,2553.92 h60
  text "ENEPIG" at 13731,2550.64 h60
  text "SURFACE FINISH:" at 11332.46,2549.64 h60
  text "IMM. TIN/SILVER OR EQUIV" at 11662,2392.64 h60
  text "OTHER" at 13093.46,2392.64 h60
  text "X" at 12209.46,2215.64 h60
  text "ARRAY/PANEL:" at 11332.46,2213.64 h60
  text "CUT AND TRIM PER MECH LAYER 1" at 12393.46,2209.35 h60
  text "N.C. ROUTE" at 12393.46,2057.64 h60
  text "V. SCORE" at 13259.46,2057.64 h60
  text "CERTIFICATION:" at 11332.46,1920.64 h60
  text "MATERIALS AND WORKMANSHIP FOR ALL PCBS" at 12057.46,1920.64 h60
  text "TO MEET OR EXCEED THE REQUIREMENTS OF:" at 12057.46,1822.64 h60
  text "X" at 11683.96,1686.13 h60
  text "ANSI IPC-A-600F CLASS ->" at 11822.96,1686.13 h60
  text "X" at 13462.02,1686.13 h60
  text "2" at 13580.96,1686.14 h60
  text "1" at 13265.96,1684.64 h60
  text "3" at 13934.96,1684.64 h60
  text "X" at 11686.02,1526.64 h60
  text "UL 94V-0" at 11822.96,1526.64 h60
  text "X" at 12498.02,1526.64 h60
  text "RoHS" at 12634.96,1526.64 h60
  text "OTHER" at 13279.36,1526.64 h60
  text "PER ORDER" at 13676.42,1526.64 h60
  text "ALL BOARDS MUST MEET OR EXCEED UL94-V0 REQUIREMENTS." at 11361,1374 h60
  text "PCB MUST BEAR THE UL94V-0 UL REGISTERED MATERIAL ID NUMBER" at 11361,1254 h60
  text "ADDITIONAL REQUIREMENTS:" at 11316.46,1142.64 h60
  text "MICROSECTION:" at 11391.23,1027.64 h60
  text "YES" at 12296.96,1027.64 h60
  text "REQUIRED" at 13158.46,871.49 h60
  text "BARE BOARD ELEC. TEST:" at 11391.23,868.64 h60
  text "NONE" at 12696.96,868.64 h60
  text "X" at 13031.46,868.64 h60
  text "PER ORDER" at 13750.46,868.64 h60
  text "MANUFACTURER'S UL:" at 11391.23,711.64 h60
  text "RAIL" at 12556.96,707.35 h60
  text "METAL" at 13048.77,707.35 h60
  text "X" at 13424,707 h60
  text "SILK" at 13560.46,707.35 h60
  text ".Layer_Name" at 577,-858.49 h60
M11 Gerber Information:
  lines w10: -292,-930.17 6308,-930.17 ; -292,-726.83 6310,-726.83 ; -292,-523.5 -292,-1133.5 3713,-1133.5 6310,-1133.5 6310,-523.5 -291.5,-523.5 -291.5,-1133.5 1284,-1133.5 ; 2173,-1133.5 2173,-523.5 ; 3440,-726.83 3440,-523.5 ; 4280,-726.83 4280,-523.5 ; 4902,-1140 4902,-937.17
  text "ALL ARTWORK VIEWED FROM TOP SIDE" at -228.5,-655.67 h60
  text "BOARD #:" at 2248,-655.67 h60
  text ".PRJ_Number" at 2793.5,-655.67 h60
  text "REV:" at 3638,-655.67 h60
  text "B" at 3929.5,-655.67 h60
  text "SVN REV:" at 4476,-655.67 h60
  text ".VersionControl_RevNumber" at 4982,-655.67 h60
  text "LAYER NAME =" at -228.5,-858.49 h60
  text "PLOT NAME =" at -228.5,-1064.34 h60
  text ".plot_File_Name" at 577,-1064.34 h60
  text "GENERATED    :" at 2250,-1064.34 h60
  text ".Print_Date" at 3119.5,-1064.34 h60
  text ".Print_Time" at 3848.5,-1064.34 h60
  text "TEXAS INSTRUMENTS" at 5113,-1064.34 h60
M12 Stackup:
  drawing of 166 lines, arcs and shapes, not listed
  text "Layer" at 9817.55,7746 h60
  text "Name" at 10227.47,7746 h60
  text "Material" at 11087.23,7746 h60
  text "Thickness" at 11947,7746 h60
  text "Constant" at 12596.84,7746 h60
  text "Board Layer Stack" at 13166.7,7746 h60
  text "1" at 9817.55,7626 h60
  text "Top Overlay" at 10227.47,7626 h60
  text "2" at 9817.55,7506 h60
  text "Top Solder" at 10227.47,7506 h60
  text "Solder Resist" at 11087.23,7506 h60
  text "0.40mil" at 11947,7506 h60
  text "3.5" at 12596.84,7506 h60
  text "3" at 9817.55,7386 h60
  text "Top Layer" at 10227.47,7386 h60
  text "Copper" at 11087.23,7386 h60
  text "2.80mil" at 11947,7386 h60
  text "4" at 9817.55,7266 h60
  text "Dielectric1" at 10227.47,7266 h60
  text "FR-4" at 11087.23,7266 h60
  text "59.20mil" at 11947,7266 h60
  text "4.8" at 12596.84,7266 h60
  text "5" at 9817.55,7146 h60
  text "Bottom Layer" at 10227.47,7146 h60
  text "Copper" at 11087.23,7146 h60
  text "2.80mil" at 11947,7146 h60
  text "6" at 9817.55,7026 h60
  text "Bottom Solder" at 10227.47,7026 h60
  text "Solder Resist" at 11087.23,7026 h60
  text "0.40mil" at 11947,7026 h60
  text "3.5" at 12596.84,7026 h60
  text ".Layer_Name" at 577,-858.49 h60
M13 Component Bodies Top:
  text ".Layer_Name" at 577,-858.49 h60
M14 Component Bodies Bottom:
  text ".Layer_Name" at 577,-858.49 h60
M15 Courtyards Top:
  text ".Layer_Name" at 577,-858.49 h60
M16 Courtyards Bottom:
  text ".Layer_Name" at 577,-858.49 h60
Drill Drawing:
  lines w10: 3265.09,1164.02 3320.34,1164.02 3320.34,1219.27 3265.09,1219.27 3265.09,1164.02 ; 3265.09,1288.34 3292.72,1302.15 3320.34,1288.34 3306.53,1315.96 3320.34,1343.59 3292.72,1329.78 3265.09,1343.59 3278.9,1315.96 3265.09,1288.34 ; 3265.09,1426.47 3278.9,1426.47 3278.9,1412.66 3306.53,1412.66 3306.53,1426.47 3320.34,1426.47 3320.34,1454.1 3306.53,1454.1 3306.53,1467.91 3278.9,1467.91 3278.9,1454.1 3265.09,1454.1 3265.09,1426.47
  lines w12: 3215,1126.72 6446.49,1126.72 ; 3215,1499.68 6446.49,1499.68 ; 3552.86,1002.4 3552.86,1624 ; 3884.86,1002.4 3884.86,1624 ; 4521.43,1002.4 4521.43,1624 ; 4780.57,1002.4 4780.57,1624 ; 5155.72,1002.4 5155.72,1624 ; 5880.05,1002.4 5880.05,1624 ; 3215,1002.4 6446.49,1002.4 6446.49,1624 3215,1624 3215,1002.4
  text "Symbol" at 3289.59,1536.98 h72
  text "Quantity" at 3590.16,1536.98 h72
  text "Finished Hole Size" at 3922.16,1536.98 h72
  text "Plated" at 4558.72,1536.98 h72
  text "Hole Type" at 4817.86,1536.98 h72
  text "Drill Layer Pair" at 5193.02,1536.98 h72
  text "Hole Tolerance" at 5917.35,1536.98 h72
  text "198" at 3590.16,1412.66 h60
  text "8.00mil (0.203mm)" at 3922.16,1412.66 h60
  text "PTH" at 4558.72,1412.66 h60
  text "Round" at 4817.86,1412.66 h60
  text "Top Layer - Bottom Layer" at 5193.02,1412.66 h60
  text "9" at 3590.16,1288.34 h60
  text "40.00mil (1.016mm)" at 3922.16,1288.34 h60
  text "PTH" at 4558.72,1288.34 h60
  text "Round" at 4817.86,1288.34 h60
  text "Top Layer - Bottom Layer" at 5193.02,1288.34 h60
  text "4" at 3590.16,1164.02 h60
  text "50.00mil (1.270mm)" at 3922.16,1164.02 h60
  text "PTH" at 4558.72,1164.02 h60
  text "Round" at 4817.86,1164.02 h60
  text "Top Layer - Bottom Layer" at 5193.02,1164.02 h60
  text "211 Total" at 3590.16,1039.7 h60
  text ".Layer_Name" at 577,-858.49 h60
